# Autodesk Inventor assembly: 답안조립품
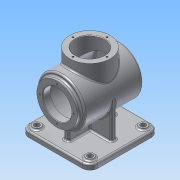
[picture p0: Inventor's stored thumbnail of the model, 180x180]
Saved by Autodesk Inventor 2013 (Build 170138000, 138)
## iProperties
Created: 2015-07
Part Number: 답안조립품
Document SubType Name: Assembly
Designer: Administrator
Author: Administrator
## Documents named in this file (2)
- C:\Users\Administrator\Desktop\450706V1005\답안조립품.iam
- C:\Users\Administrator\Desktop\450706V1005\본체.ipt
